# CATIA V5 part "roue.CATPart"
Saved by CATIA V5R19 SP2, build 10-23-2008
Part number: roue
Bounding box of the stored display mesh (mm): x -300 to 300, y -70 to 70, z -300 to 300
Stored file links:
  M:\EU_thinkMotion\IAO_2010\iao\IAO_MMS_Groupe2\IAO_MMS_Groupe2\mayache\mayache\Pièces\roue.CATPart
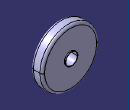
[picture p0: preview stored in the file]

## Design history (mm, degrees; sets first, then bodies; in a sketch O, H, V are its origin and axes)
Parameters
  rayroue = 300 mm
  eproue = 120 mm
  trou = 60 mm
Body1 (main body)
  Sketch1 on zx-plane, origin (0, 0, 0), H (-1, 0, 0), V (0, 0, 1)
    circle A1 centre (0, 0) radius 300
    radius A1 = 300 {= rayroue}
  Pad1: profile Sketch1, direction (0, 1, 0), length 60 {= eproue /2}, mirrored extent
  Fillet1: radius 25, on edge [start face of Pad1 | face of Pad1 from Sketch1.A1]; edge [face of Pad1 from Sketch1.A1 | end face of Pad1]
  Sketch2 on start face of Pad1, origin (0, -60, 0), H (1, 0, 0), V (0, 0, 1)
    circle A1 centre (0, 0) radius 66
    point P1 (66, 0)
    radius A1 = 66 {= trou +(trou /10)}
    coincidence: A1 P1, P1 H
  Pad2: profile Sketch2, direction (0, -1, 0), length 10
  Mirror1: of Pad2, about zx-plane
  Body2
    Sketch3 on zx-plane, origin (0, 0, 0), H (-1, 0, 0), V (0, 0, 1)
      circle A1 centre (0, 0) radius 60
      radius A1 = 60 {= trou}
    Pad3: profile Sketch3, direction (0, 1, 0), length 200, mirrored extent
  Remove1: tool Body2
